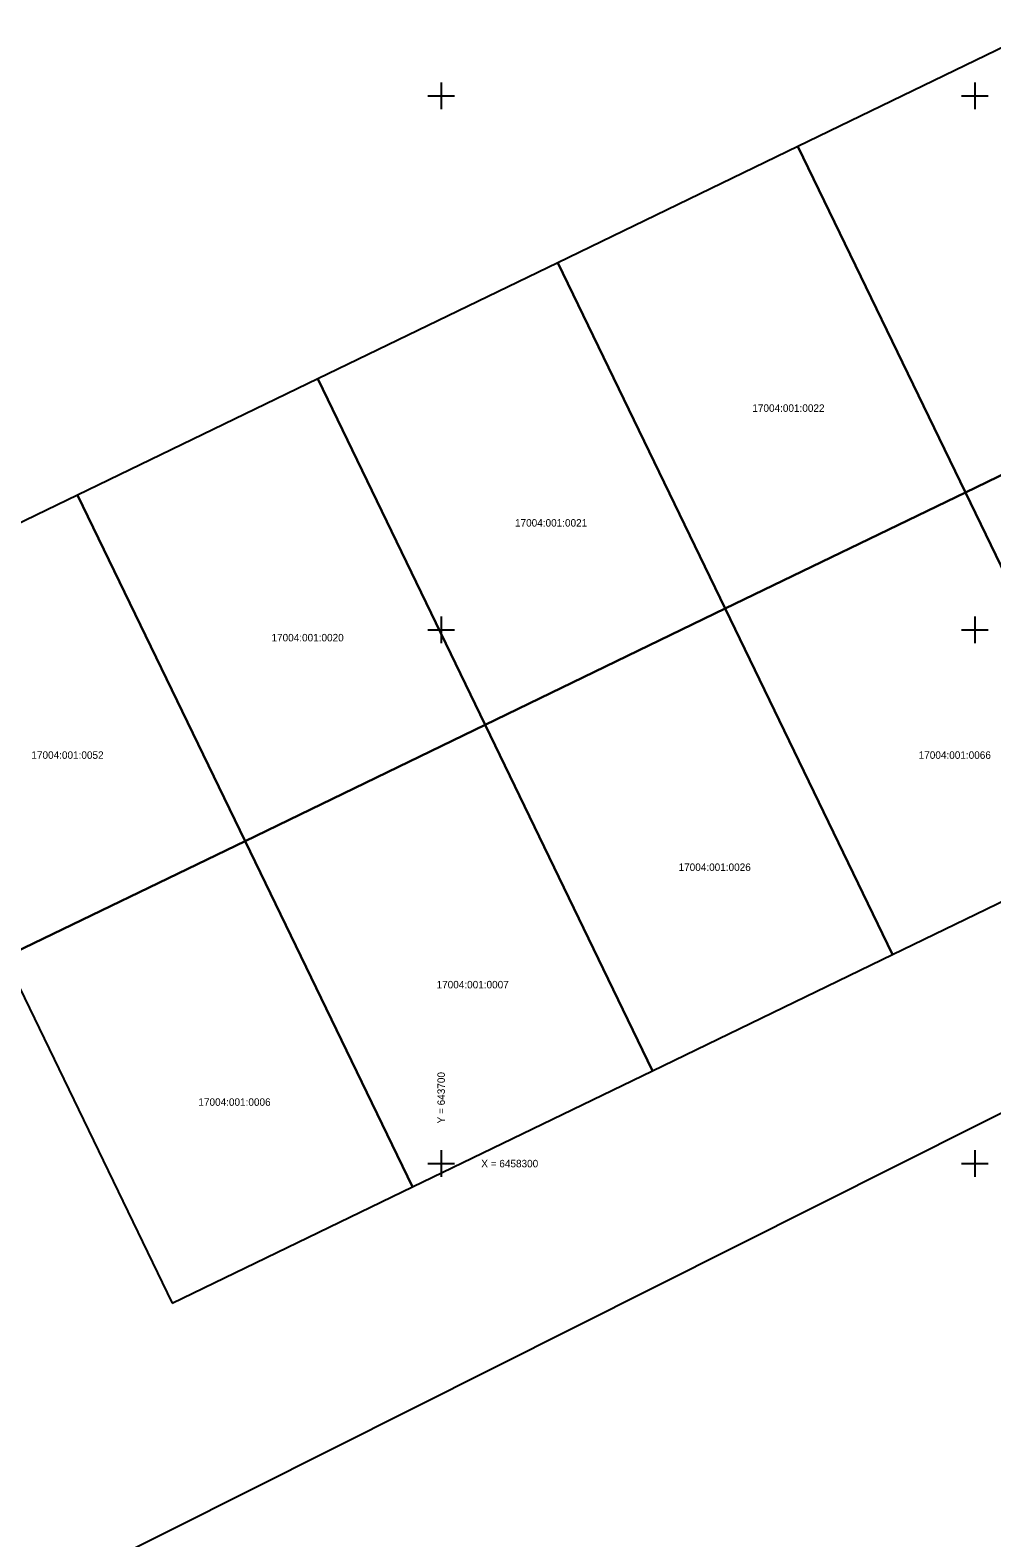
# Model space of a CAD drawing. Extents: x 643307 to 644029, y 6457938 to 6458417.
# Drawn here: x 643661.5 to 643751.6, y 6458264.9 to 6458406.2 of the extents above; entities that cross this region are included whole.
import ezdxf

# ---------------------------------------------------------------- set-up
doc = ezdxf.new("R2010")
doc.units = 0
for name, color, linetype in [('30_TEE', 7, 'Continuous'), ('40_PIIR', 7, 'Continuous'), ('63_VORK', 7, 'Continuous')]:
    doc.layers.add(name, color=color, linetype=linetype)

# ---------------------------------------------------------------- blocks, each defined once
blk = doc.blocks.new('VKORIS')
at = {"layer": '30_TEE'}
for p, q in [((-2.5, 0), (2.5, 0)), ((0, 2.5), (0, -2.5))]:
    blk.add_line(p, q, dxfattribs=at)

msp = doc.modelspace()

# ---------------------------------------------------------------- linework, layer by layer
at = {"layer": '40_PIIR'}
for points in [[(643755.95, 6458406.16), (643733.44, 6458395.27), (643749.13, 6458362.87), (643771.63, 6458373.76)], [(643733.44, 6458395.27), (643710.94, 6458384.38), (643726.62, 6458351.99), (643749.13, 6458362.87)], [(643710.94, 6458384.38), (643688.44, 6458373.5), (643704.12, 6458341.1), (643726.62, 6458351.99)], [(643773.37, 6458370.16), (643795.88, 6458381.05), (643794.13, 6458384.65), (643771.63, 6458373.76), (643749.13, 6458362.87), (643764.81, 6458330.47), (643787.31, 6458341.36), (643783.83, 6458348.56)], [(643688.44, 6458373.5), (643665.93, 6458362.61), (643681.62, 6458330.21), (643704.12, 6458341.1)], [(643665.93, 6458362.61), (643643.43, 6458351.73), (643659.11, 6458319.33), (643681.62, 6458330.21)], [(643742.31, 6458319.59), (643764.81, 6458330.47), (643749.13, 6458362.87), (643726.62, 6458351.99)], [(643719.8, 6458308.7), (643742.31, 6458319.59), (643726.62, 6458351.99), (643704.12, 6458341.1)], [(643697.3, 6458297.82), (643719.8, 6458308.7), (643704.12, 6458341.1), (643681.62, 6458330.21)], [(643674.8, 6458286.93), (643697.3, 6458297.82), (643681.62, 6458330.21), (643659.11, 6458319.33)]]:
    msp.add_lwpolyline(points, close=True, dxfattribs=at)
msp.add_lwpolyline([(643948.83, 6458373.13), (643834.5, 6458327.04), (643809.94, 6458318.75), (643757.99, 6458307.46), (643667.02, 6458261.82), (643682.1, 6458226.44), (643640.7, 6458203.32)], dxfattribs=at)

# ---------------------------------------------------------------- block references
at = {"layer": '63_VORK', "xscale": 0.5, "yscale": 0.5}
for p in [(643700, 6458400), (643750, 6458400), (643700, 6458350), (643750, 6458350), (643700, 6458300), (643750, 6458300)]:
    msp.add_blockref('VKORIS', p, dxfattribs=at)

# ---------------------------------------------------------------- texts
at = {"layer": '40_PIIR'}
for s, p in [('17004:001:0022', (643729.16, 6458370.41)), ('17004:001:0021', (643706.92, 6458359.66)), ('17004:001:0020', (643684.1, 6458348.91)), ('17004:001:0052', (643661.6, 6458337.91)), ('17004:001:0066', (643744.75, 6458337.91)), ('17004:001:0026', (643722.25, 6458327.41)), ('17004:001:0007', (643699.57, 6458316.41)), ('17004:001:0006', (643677.25, 6458305.41))]:
    msp.add_text(s, height=0.7, dxfattribs=at).set_placement(p)
at = {"layer": '63_VORK'}
msp.add_text(' Y = 643700', height=0.7, rotation=90, dxfattribs=at).set_placement((643700.35, 6458303.5))
msp.add_text(' X = 6458300', height=0.7, dxfattribs=at).set_placement((643703.5, 6458299.65))

doc.saveas('drawing.dxf')
